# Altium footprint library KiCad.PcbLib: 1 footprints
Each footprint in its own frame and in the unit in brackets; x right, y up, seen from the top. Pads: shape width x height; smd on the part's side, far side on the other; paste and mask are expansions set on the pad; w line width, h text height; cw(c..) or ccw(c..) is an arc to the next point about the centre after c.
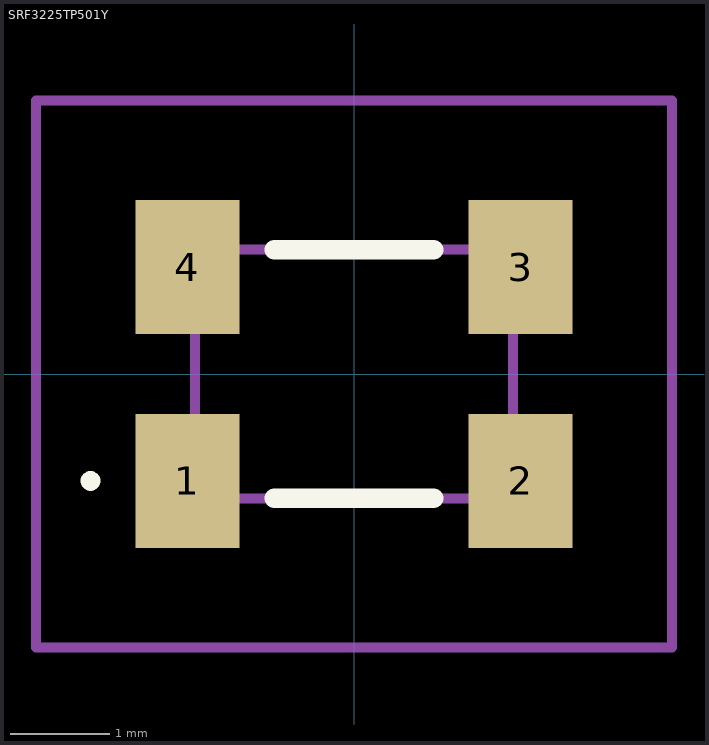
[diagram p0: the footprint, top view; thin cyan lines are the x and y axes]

## SRF3225TP501Y [mm]
pads (4):
  rect 1.05x1.35 smd: 1(-1.675,-1.075) 2(1.675,-1.075) 3(1.675,1.075) 4(-1.675,1.075)
F.SilkS:
  lines w0.1: -2.7,-1.075 ccw(c-2.65,-1.075) -2.6,-1.075 ccw(c-2.65,-1.075) -2.7,-1.075
  lines w0.2: -0.8,-1.25 0.8,-1.25 ; -0.8,1.25 0.8,1.25
F.CrtYd:
  lines w0.1: -3.2,-2.75 3.2,-2.75 3.2,2.75 -3.2,2.75 -3.2,-2.75
F.Fab:
  lines w0.1: -1.6,-1.25 1.6,-1.25 1.6,1.25 -1.6,1.25 -1.6,-1.25
  text "'.Designator'" at -5.203,-1.131 h1.27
